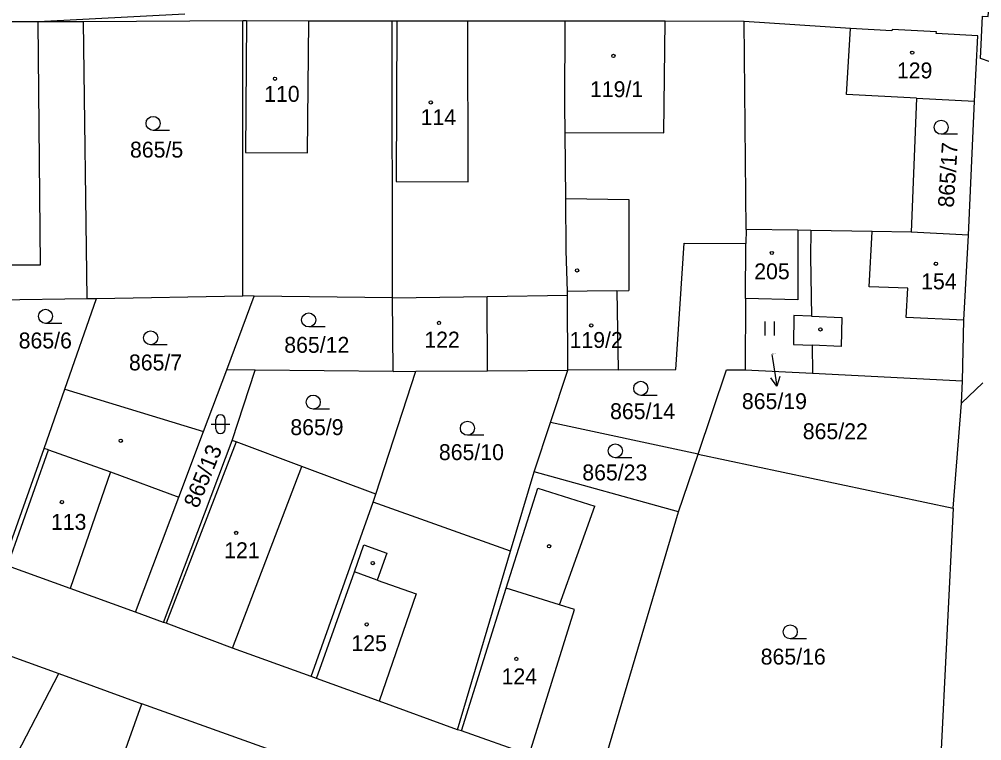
# Model space of a CAD drawing. Extents: x -801826 to -800592, y -1032871 to -1031813.
# Drawn here: x -800933.1 to -800830.2, y -1032457.9 to -1032380.8 of the extents above; entities that cross this region are included whole.
import ezdxf

# ---------------------------------------------------------------- set-up
doc = ezdxf.new("R2010")
doc.units = 0
for name, color, linetype in [('Vrstva 1', 7, 'Continuous'), ('Vrstva 16', 7, 'Continuous'), ('Vrstva 18', 7, 'Continuous'), ('Vrstva 19', 7, 'Continuous'), ('Vrstva 25', 7, 'Continuous'), ('Vrstva 27', 7, 'Continuous'), ('Vrstva 4', 7, 'Continuous')]:
    doc.layers.add(name, color=color, linetype=linetype)

msp = doc.modelspace()

# ---------------------------------------------------------------- linework, layer by layer
at = {"layer": 'Vrstva 1'}
for p, q in [((-800915.4, -1032380.25), (-800931.09, -1032381.06)), ((-800931.09, -1032381.06), (-800939.18, -1032381.05)), ((-800926.26, -1032381.05), (-800931.09, -1032381.06)), ((-800909.23, -1032380.97), (-800926.26, -1032381.05)), ((-800925.85, -1032410.64), (-800926.26, -1032381.05)), ((-800908.83, -1032380.97), (-800909.23, -1032380.97)), ((-800909.22, -1032410.37), (-800909.23, -1032380.97)), ((-800902.16, -1032380.98), (-800908.83, -1032380.97)), ((-800893.26, -1032380.99), (-800902.16, -1032380.98)), ((-800892.76, -1032380.99), (-800893.26, -1032380.99)), ((-800893.22, -1032410.56), (-800893.26, -1032380.99)), ((-800885.18, -1032380.99), (-800892.76, -1032380.99)), ((-800874.76, -1032380.98), (-800885.18, -1032380.99)), ((-800874.79, -1032390.01), (-800874.76, -1032380.98)), ((-800864.08, -1032380.98), (-800874.76, -1032380.98)), ((-800855.62, -1032381.03), (-800864.08, -1032380.98)), ((-800844.27, -1032381.78), (-800855.62, -1032381.03)), ((-800855.4, -1032403.28), (-800855.62, -1032381.03)), ((-800839.83, -1032382.04), (-800844.27, -1032381.78)), ((-800839.82, -1032381.87), (-800839.83, -1032382.04)), ((-800835.08, -1032382.15), (-800839.82, -1032381.87)), ((-800835.09, -1032382.32), (-800835.08, -1032382.15)), ((-800830.65, -1032382.58), (-800835.09, -1032382.32)), ((-800831.01, -1032389.55), (-800830.65, -1032382.58)), ((-800837.22, -1032389.23), (-800837.77, -1032403.55)), ((-800837.22, -1032389.23), (-800831.01, -1032389.55)), ((-800831.65, -1032403.89), (-800831.01, -1032389.55)), ((-800874.76, -1032392.88), (-800874.79, -1032390.01)), ((-800874.69, -1032399.96), (-800874.76, -1032392.88)), ((-800874.69, -1032399.96), (-800867.97, -1032400.07)), ((-800874.64, -1032405.5), (-800874.69, -1032399.96)), ((-800867.97, -1032400.07), (-800867.95, -1032409.8)), ((-800855.4, -1032403.28), (-800855.45, -1032404.76)), ((-800849.9, -1032403.35), (-800855.4, -1032403.28)), ((-800848.49, -1032403.37), (-800849.9, -1032403.35)), ((-800849.9, -1032403.35), (-800849.88, -1032410.79)), ((-800848.49, -1032403.37), (-800848.54, -1032406.15)), ((-800841.96, -1032403.48), (-800848.49, -1032403.37)), ((-800837.77, -1032403.55), (-800841.96, -1032403.48)), ((-800831.65, -1032403.89), (-800837.77, -1032403.55)), ((-800832.16, -1032412.95), (-800831.65, -1032403.89)), ((-800862.94, -1032418.24), (-800862.05, -1032404.72)), ((-800862.05, -1032404.72), (-800855.45, -1032404.76)), ((-800855.48, -1032410.64), (-800855.45, -1032404.76)), ((-800874.52, -1032409.9), (-800874.64, -1032405.5)), ((-800848.54, -1032406.15), (-800848.42, -1032412.53)), ((-800874.52, -1032410.3), (-800874.52, -1032409.9)), ((-800869.23, -1032409.82), (-800867.95, -1032409.8)), ((-800869.23, -1032409.82), (-800869.1, -1032418.27)), ((-800939.55, -1032410.87), (-800925.85, -1032410.64)), ((-800928.24, -1032420.34), (-800924.85, -1032410.63)), ((-800925.85, -1032410.64), (-800924.85, -1032410.63)), ((-800924.85, -1032410.63), (-800909.22, -1032410.37)), ((-800910.93, -1032418.26), (-800908.02, -1032410.38)), ((-800908.02, -1032410.38), (-800909.22, -1032410.37)), ((-800893.22, -1032410.56), (-800908.02, -1032410.38)), ((-800893.22, -1032410.56), (-800883.11, -1032410.42)), ((-800893.13, -1032418.45), (-800893.22, -1032410.56)), ((-800883.11, -1032410.42), (-800874.52, -1032410.3)), ((-800874.48, -1032418.3), (-800874.52, -1032410.3)), ((-800855.48, -1032410.64), (-800855.52, -1032418.26)), ((-800849.88, -1032410.79), (-800855.48, -1032410.64)), ((-800850.3, -1032412.45), (-800850.37, -1032415.55)), ((-800848.42, -1032412.53), (-800850.3, -1032412.45)), ((-800832.28, -1032419.46), (-800832.16, -1032412.95)), ((-800850.37, -1032415.55), (-800848.37, -1032415.64)), ((-800848.37, -1032415.64), (-800848.31, -1032418.63)), ((-800913.43, -1032424.87), (-800910.93, -1032418.26)), ((-800907.91, -1032418.29), (-800910.93, -1032418.26)), ((-800910.35, -1032425.81), (-800907.91, -1032418.29)), ((-800893.13, -1032418.45), (-800907.91, -1032418.29)), ((-800894.99, -1032431.56), (-800890.74, -1032418.43)), ((-800893.13, -1032418.45), (-800890.74, -1032418.43)), ((-800890.74, -1032418.43), (-800883.05, -1032418.37)), ((-800883.05, -1032418.37), (-800874.48, -1032418.3)), ((-800876.34, -1032423.91), (-800874.48, -1032418.3)), ((-800869.1, -1032418.27), (-800874.48, -1032418.3)), ((-800869.1, -1032418.27), (-800862.94, -1032418.24)), ((-800860.53, -1032427.27), (-800857.53, -1032418.26)), ((-800857.53, -1032418.26), (-800855.52, -1032418.26)), ((-800855.52, -1032418.26), (-800848.31, -1032418.63)), ((-800848.31, -1032418.63), (-800832.28, -1032419.46)), ((-800832.38, -1032421.83), (-800832.28, -1032419.46)), ((-800930.45, -1032426.67), (-800928.24, -1032420.34)), ((-800928.24, -1032420.34), (-800913.43, -1032424.87)), ((-800832.38, -1032421.83), (-800830.13, -1032419.65)), ((-800833.28, -1032433.06), (-800832.38, -1032421.83)), ((-800878.08, -1032429.17), (-800876.34, -1032423.91)), ((-800860.53, -1032427.27), (-800876.34, -1032423.91)), ((-800916.06, -1032431.88), (-800913.43, -1032424.87)), ((-800934.84, -1032439.06), (-800930.45, -1032426.67)), ((-800917.7, -1032445.27), (-800910.35, -1032425.81)), ((-800909.93, -1032425.97), (-800910.35, -1032425.81)), ((-800902.9, -1032428.6), (-800909.93, -1032425.97)), ((-800862.65, -1032433.45), (-800860.53, -1032427.27)), ((-800860.53, -1032427.27), (-800833.28, -1032433.06)), ((-800894.99, -1032431.56), (-800902.9, -1032428.6)), ((-800880.61, -1032437.67), (-800878.08, -1032429.17)), ((-800862.65, -1032433.45), (-800878.08, -1032429.17)), ((-800895.27, -1032432.41), (-800894.99, -1032431.56)), ((-800920.7, -1032444.18), (-800916.06, -1032431.88)), ((-800901.9, -1032451.07), (-800895.27, -1032432.41)), ((-800880.61, -1032437.67), (-800895.27, -1032432.41)), ((-800871.14, -1032462.11), (-800862.65, -1032433.45)), ((-800833.28, -1032433.06), (-800835.24, -1032471.87)), ((-800886.27, -1032456.75), (-800880.61, -1032437.67)), ((-800927.67, -1032441.66), (-800934.37, -1032439.23)), ((-800920.7, -1032444.18), (-800927.67, -1032441.66)), ((-800917.7, -1032445.27), (-800920.7, -1032444.18)), ((-800917.42, -1032445.37), (-800917.7, -1032445.27)), ((-800910.31, -1032448.02), (-800917.42, -1032445.37)), ((-800901.9, -1032451.07), (-800910.31, -1032448.02)), ((-800933.9, -1032448.93), (-800928.9, -1032450.72)), ((-800938.09, -1032468.54), (-800928.9, -1032450.72)), ((-800928.9, -1032450.72), (-800920.01, -1032453.97)), ((-800901.34, -1032451.27), (-800901.9, -1032451.07)), ((-800894.66, -1032453.68), (-800901.34, -1032451.27)), ((-800927.61, -1032475.17), (-800920.01, -1032453.97)), ((-800895.05, -1032462.91), (-800920.01, -1032453.97)), ((-800886.27, -1032456.75), (-800894.66, -1032453.68)), ((-800885.84, -1032456.88), (-800886.27, -1032456.75)), ((-800878.62, -1032459.44), (-800885.84, -1032456.88))]:
    msp.add_line(p, q, dxfattribs=at)
at = {"layer": 'Vrstva 16'}
for p, q in [((-800852.67, -1032416.62), (-800852.6, -1032417.07)), ((-800852.6, -1032417.07), (-800852.14, -1032420.03))]:
    msp.add_line(p, q, dxfattribs=at)
msp.add_lwpolyline([(-800851.8, -1032418.97), (-800852.14, -1032420.03), (-800852.79, -1032419.12)], dxfattribs=at)
at = {"layer": 'Vrstva 25'}
for p, q in [((-800917.06, -1032392.67), (-800918.81, -1032392.67)), ((-800832.82, -1032393.09), (-800834.57, -1032393.09)), ((-800928.56, -1032413.3), (-800930.31, -1032413.3)), ((-800853.4, -1032413.1), (-800853.4, -1032414.6)), ((-800852.38, -1032414.6), (-800852.38, -1032413.1)), ((-800900.43, -1032413.69), (-800902.18, -1032413.69)), ((-800917.32, -1032415.6), (-800919.07, -1032415.6)), ((-800864.93, -1032421), (-800866.68, -1032421)), ((-800899.94, -1032422.47), (-800901.69, -1032422.47)), ((-800912.11, -1032424.58), (-800912.11, -1032423.58)), ((-800911.11, -1032424.58), (-800911.11, -1032423.58)), ((-800912.61, -1032424.08), (-800910.61, -1032424.08)), ((-800883.46, -1032425.27), (-800885.21, -1032425.27)), ((-800867.65, -1032427.68), (-800869.4, -1032427.68)), ((-800848.95, -1032447.03), (-800850.7, -1032447.03))]:
    msp.add_line(p, q, dxfattribs=at)
for centre, radius in [((-800837.66, -1032384.36), 0.175), ((-800869.6, -1032384.71), 0.175), ((-800905.78, -1032387.15), 0.175), ((-800889.13, -1032389.68), 0.175), ((-800918.81, -1032391.92), 0.75), ((-800834.57, -1032392.34), 0.75), ((-800852.67, -1032405.78), 0.175), ((-800835.13, -1032406.93), 0.175), ((-800873.49, -1032407.65), 0.175), ((-800930.31, -1032412.55), 0.75), ((-800902.18, -1032412.94), 0.75), ((-800888.25, -1032413.25), 0.175), ((-800919.07, -1032414.85), 0.75), ((-800871.97, -1032413.53), 0.175), ((-800847.48, -1032413.95), 0.175), ((-800866.68, -1032420.25), 0.75), ((-800901.69, -1032421.72), 0.75), ((-800885.21, -1032424.52), 0.75), ((-800922.26, -1032425.85), 0.175), ((-800869.4, -1032426.93), 0.75), ((-800928.56, -1032432.41), 0.175), ((-800909.93, -1032435.71), 0.175), ((-800876.48, -1032437.13), 0.175), ((-800895.33, -1032438.93), 0.175), ((-800895.98, -1032445.49), 0.175), ((-800850.7, -1032446.28), 0.75), ((-800879.98, -1032449.18), 0.175)]:
    msp.add_circle(centre, radius, dxfattribs=at)
for centre, start, end in [((-800911.61, -1032423.58), 0, 180), ((-800911.61, -1032424.58), 180, 0)]:
    msp.add_arc(centre, 0.5, start, end, dxfattribs=at)
at = {"layer": 'Vrstva 27'}
msp.add_lwpolyline([(-800829.45, -1032379.12), (-800828.85, -1032379.18), (-800829.34, -1032385.34), (-800830.35, -1032384.99), (-800830.15, -1032380.47), (-800829.55, -1032380.49), (-800829.45, -1032379.12)], dxfattribs=at)
at = {"layer": 'Vrstva 4'}
for p, q in [((-800930.83, -1032407.06), (-800931.09, -1032381.06)), ((-800908.83, -1032380.97), (-800908.92, -1032395.03)), ((-800902.29, -1032395.07), (-800902.16, -1032380.98)), ((-800892.76, -1032380.99), (-800892.81, -1032398.15)), ((-800885.13, -1032398.17), (-800885.18, -1032380.99)), ((-800864.23, -1032392.94), (-800864.08, -1032380.98)), ((-800844.68, -1032388.84), (-800844.27, -1032381.78)), ((-800837.22, -1032389.23), (-800844.68, -1032388.84)), ((-800874.76, -1032392.88), (-800864.23, -1032392.94)), ((-800908.92, -1032395.03), (-800902.29, -1032395.07)), ((-800892.81, -1032398.15), (-800885.13, -1032398.17)), ((-800842.26, -1032409.39), (-800841.96, -1032403.48)), ((-800938.94, -1032407.04), (-800930.83, -1032407.06)), ((-800872.42, -1032409.87), (-800874.52, -1032409.9)), ((-800869.23, -1032409.82), (-800872.42, -1032409.87)), ((-800838.12, -1032409.53), (-800842.26, -1032409.39)), ((-800838.31, -1032412.66), (-800838.12, -1032409.53)), ((-800883.05, -1032418.37), (-800883.11, -1032410.42)), ((-800848.42, -1032412.53), (-800845.17, -1032412.67)), ((-800845.17, -1032412.67), (-800845.25, -1032415.78)), ((-800832.16, -1032412.95), (-800838.31, -1032412.66)), ((-800845.25, -1032415.78), (-800848.37, -1032415.64)), ((-800929.98, -1032426.83), (-800930.45, -1032426.67)), ((-800909.93, -1032425.97), (-800917.42, -1032445.37)), ((-800934.37, -1032439.23), (-800929.98, -1032426.83)), ((-800929.98, -1032426.83), (-800923.38, -1032429.17)), ((-800910.31, -1032448.02), (-800902.9, -1032428.6)), ((-800923.38, -1032429.17), (-800927.67, -1032441.66)), ((-800923.38, -1032429.17), (-800916.06, -1032431.88)), ((-800881.06, -1032441.63), (-800877.7, -1032430.92)), ((-800877.7, -1032430.92), (-800871.59, -1032432.84)), ((-800875.37, -1032443.41), (-800871.59, -1032432.84)), ((-800897.29, -1032439.87), (-800896.27, -1032436.99)), ((-800896.27, -1032436.99), (-800893.82, -1032437.87)), ((-800893.82, -1032437.87), (-800894.84, -1032440.74)), ((-800901.34, -1032451.27), (-800897.29, -1032439.87)), ((-800894.84, -1032440.74), (-800897.29, -1032439.87)), ((-800894.84, -1032440.74), (-800890.69, -1032442.21)), ((-800885.84, -1032456.88), (-800881.06, -1032441.63)), ((-800875.37, -1032443.41), (-800881.06, -1032441.63)), ((-800890.69, -1032442.21), (-800894.66, -1032453.68)), ((-800878.62, -1032459.44), (-800873.76, -1032443.91)), ((-800873.76, -1032443.91), (-800875.37, -1032443.41))]:
    msp.add_line(p, q, dxfattribs=at)

# ---------------------------------------------------------------- texts
at = {"layer": 'Vrstva 16'}
msp.add_text('865/19', height=1.7, dxfattribs=at).set_placement((-800855.87, -1032422.47))
at = {"layer": 'Vrstva 18'}
for s, height, p in [('865/5', 1.7, (-800921.28, -1032395.58)), ('865/6', 1.7, (-800933.18, -1032415.98)), ('865/12', 1.7, (-800904.79, -1032416.45)), ('865/7', 1.7, (-800921.39, -1032418.33)), ('865/19', 0.1, (-800852.67, -1032416.62)), ('865/14', 1.7, (-800869.96, -1032423.54)), ('865/9', 1.7, (-800904.14, -1032425.25)), ('865/22', 1.7, (-800849.36, -1032425.69)), ('865/10', 1.7, (-800888.26, -1032427.92)), ('865/23', 1.7, (-800872.93, -1032430.09)), ('865/16', 1.7, (-800853.86, -1032449.78))]:
    msp.add_text(s, height=height, dxfattribs=at).set_placement(p)
for s, rotation, p in [('865/17', 86.3234, (-800833.23, -1032400.96)), ('865/13', 67.867, (-800914.02, -1032433.16))]:
    msp.add_text(s, height=1.7, rotation=rotation, dxfattribs=at).set_placement(p)
at = {"layer": 'Vrstva 19'}
for s, p in [('129', (-800839.3, -1032387.11)), ('119/1', (-800872.11, -1032389.12)), ('110', (-800906.94, -1032389.62)), ('114', (-800890.21, -1032392.11)), ('205', (-800854.55, -1032408.59)), ('154', (-800836.71, -1032409.66)), ('122', (-800889.82, -1032415.89)), ('119/2', (-800874.29, -1032415.93)), ('113', (-800929.73, -1032435.38)), ('121', (-800911.21, -1032438.41)), ('125', (-800897.61, -1032448.34)), ('124', (-800881.56, -1032451.89))]:
    msp.add_text(s, height=1.7, dxfattribs=at).set_placement(p)

doc.saveas('drawing.dxf')
